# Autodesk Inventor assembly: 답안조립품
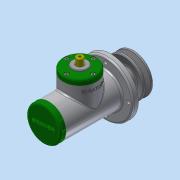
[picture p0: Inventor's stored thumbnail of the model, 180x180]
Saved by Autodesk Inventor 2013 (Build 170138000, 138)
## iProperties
Created: 2016-08
Part Number: 답안조립품
Document SubType Name: Assembly
Designer: dgall
Author: dgall
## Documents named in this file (23)
- C:\Users\dgall\Desktop\460807V1029\답안조립품.iam
- C:\Users\dgall\Desktop\460807V1029\본체.ipt
- C:\Users\dgall\Desktop\460807V1029\공용부품\V-벨트풀리.ipt
- C:\Users\dgall\Desktop\460807V1029\공용부품\너트 M10.ipt
- C:\Users\dgall\Desktop\460807V1029\공용부품\링크.ipt
- C:\Users\dgall\Desktop\460807V1029\공용부품\멈춤링 15 x 1.ipt
- C:\Users\dgall\Desktop\460807V1029\공용부품\멈춤링 35x1.6.ipt
- C:\Users\dgall\Desktop\460807V1029\공용부품\베어링 15 x 35 x 11.ipt
- C:\Users\dgall\Desktop\460807V1029\공용부품\볼트 M4 x 12.ipt
- C:\Users\dgall\Desktop\460807V1029\공용부품\부시1.ipt
- C:\Users\dgall\Desktop\460807V1029\공용부품\부시2.ipt
- C:\Users\dgall\Desktop\460807V1029\공용부품\사이드 커버.ipt
- 사이드 커버.ipt
- C:\Users\dgall\Desktop\460807V1029\공용부품\슬라이더.ipt
- C:\Users\dgall\Desktop\460807V1029\공용부품\오일 실 15 25 7.ipt
- C:\Users\dgall\Desktop\460807V1029\공용부품\와셔 4x16.ipt
- C:\Users\dgall\Desktop\460807V1029\공용부품\와셔 10x21.ipt
- C:\Users\dgall\Desktop\460807V1029\공용부품\클래스터 핀 6 x 24.ipt
- C:\Users\dgall\Desktop\460807V1029\공용부품\키 4 x 4 x 18.ipt
- C:\Users\dgall\Desktop\460807V1029\공용부품\탑 부시.ipt
- C:\Users\dgall\Desktop\460807V1029\공용부품\탑 커버.ipt
- 탑 커버.ipt
- C:\Users\dgall\Desktop\460807V1029\공용부품\편심축.ipt
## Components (5 placed, 2 different names)
1. V-벨트풀리:1
2. ISO 4762 M4 x 12:1
3. ISO 4762 M4 x 12:2
4. ISO 4762 M4 x 12:3
5. ISO 4762 M4 x 12:4
